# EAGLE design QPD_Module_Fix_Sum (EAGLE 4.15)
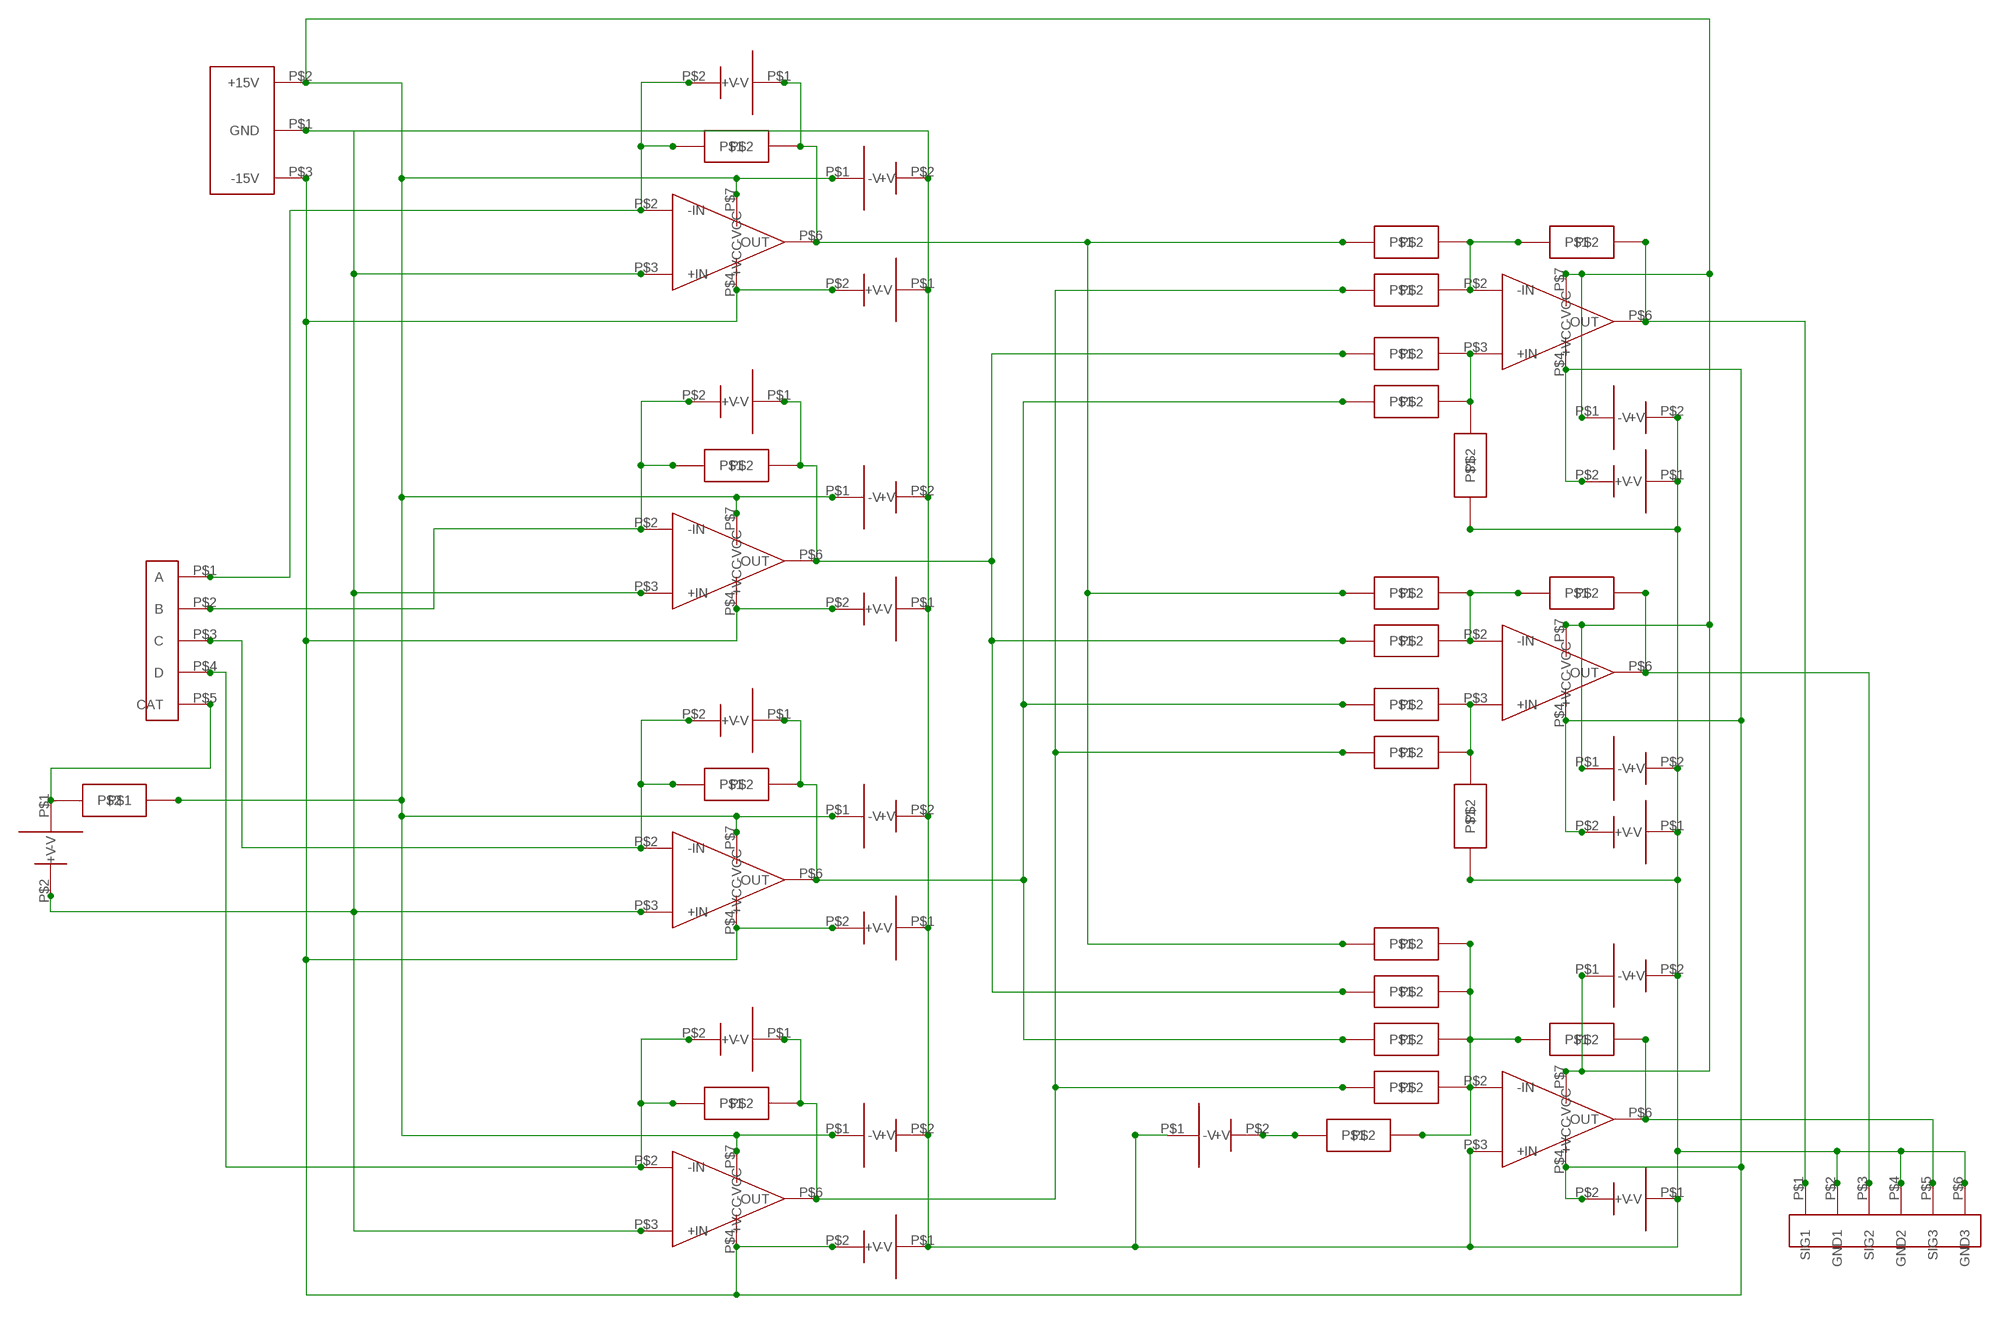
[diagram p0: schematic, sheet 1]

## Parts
U$1  OPA37GP  [OPA37GP]
U$2  OPA37GP  [OPA37GP]
U$3  OPA37GP  [OPA37GP]
U$4  OPA37GP  [OPA37GP]
U$5  OPA37GP  [OPA37GP]
U$6  OPA37GP  [OPA37GP]
U$7  OPA37GP  [OPA37GP]
U$8  PWR-CONN  [PWR-CONN]
U$9  CAP  [CAP]
U$10  RES  [RES]
U$11  CAP  [CAP]
U$12  RES  [RES]
U$13  5-TMBLK  [5-TMBLK]
U$14  CAP  [CAP]
U$15  RES  [RES]
U$16  RES  [RES]
U$17  CAP  [CAP]
U$18  6-TMBLK  [6-TMBLK]
U$19  RES  [RES]
U$20  RES  [RES]
U$21  CAP  [CAP]
U$22  CAP  [CAP]
U$23  CAP  [CAP]
U$24  CAP  [CAP]
U$25  CAP  [CAP]
U$26  CAP  [CAP]
U$27  CAP  [CAP]
U$28  CAP  [CAP]
U$29  CAP  [CAP]
U$30  RES  [RES]
U$31  RES  [RES]
U$32  RES  [RES]
U$33  RES  [RES]
U$34  RES  [RES]
U$35  RES  [RES]
U$36  RES  [RES]
U$37  RES  [RES]
U$38  RES  [RES]
U$39  RES  [RES]
U$40  RES  [RES]
U$41  RES  [RES]
U$42  RES  [RES]
U$43  RES  [RES]
U$44  RES  [RES]
U$45  RES  [RES]
U$46  RES  [RES]
U$47  CAP  [CAP]
U$48  CAP  [CAP]
U$49  CAP  [CAP]
U$50  CAP  [CAP]
U$51  CAP  [CAP]
U$52  CAP  [CAP]
U$53  CAP  [CAP]

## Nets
N$1: U$1.P$6(OUT) U$9.P$1(+V) U$10.P$2 U$32.P$1 U$34.P$1 U$42.P$1
N$2: U$19.P$1 U$53.P$2(-V)
N$4: U$13.P$5(CAT) U$20.P$2 U$21.P$1(+V)
N$6: U$5.P$3(+IN) U$32.P$2 U$33.P$2 U$38.P$2
N$7: U$1.P$3(+IN) U$2.P$3(+IN) U$3.P$3(+IN) U$4.P$3(+IN) U$7.P$3(+IN) U$8.P$1(GND) U$18.P$2(GND1) U$18.P$4(GND2) U$18.P$6(GND3) U$21.P$2(-V) U$22.P$2(-V) U$23.P$1(+V) U$24.P$2(-V) U$25.P$1(+V) U$26.P$2(-V) U$27.P$1(+V) U$28.P$1(+V) U$29.P$2(-V) U$38.P$1 U$39.P$1 U$47.P$2(-V) U$48.P$1(+V) U$49.P$2(-V) U$50.P$1(+V) U$51.P$2(-V) U$52.P$1(+V) U$53.P$1(+V)
N$8: U$1.P$2(-IN) U$9.P$2(-V) U$10.P$1 U$13.P$2(B)
N$9: U$4.P$6(OUT) U$16.P$2 U$17.P$1(+V) U$30.P$1 U$35.P$1 U$43.P$1
N$10: U$4.P$2(-IN) U$13.P$1(A) U$16.P$1 U$17.P$2(-V)
N$11: U$2.P$6(OUT) U$11.P$1(+V) U$12.P$2 U$33.P$1 U$36.P$1 U$41.P$1
N$12: U$2.P$2(-IN) U$11.P$2(-V) U$12.P$1 U$13.P$3(C)
N$13: U$3.P$6(OUT) U$14.P$1(+V) U$15.P$2 U$31.P$1 U$37.P$1 U$40.P$1
N$14: U$3.P$2(-IN) U$13.P$4(D) U$14.P$2(-V) U$15.P$1
N$15: U$5.P$2(-IN) U$30.P$2 U$31.P$2 U$44.P$1
N$17: U$6.P$3(+IN) U$36.P$2 U$37.P$2 U$39.P$2
N$19: U$7.P$2(-IN) U$19.P$2 U$40.P$2 U$41.P$2 U$42.P$2 U$43.P$2 U$46.P$1
N$21: U$1.P$7(+VCC) U$2.P$7(+VCC) U$3.P$7(+VCC) U$4.P$7(+VCC) U$5.P$7(+VCC) U$6.P$7(+VCC) U$7.P$7(+VCC) U$8.P$2(+15V) U$20.P$1 U$22.P$1(+V) U$24.P$1(+V) U$26.P$1(+V) U$29.P$1(+V) U$47.P$1(+V) U$49.P$1(+V) U$51.P$1(+V)
N$24: U$5.P$6(OUT) U$18.P$1(SIG1) U$44.P$2
N$26: U$1.P$4(-VCC) U$2.P$4(-VCC) U$3.P$4(-VCC) U$4.P$4(-VCC) U$5.P$4(-VCC) U$6.P$4(-VCC) U$7.P$4(-VCC) U$8.P$3(-15V) U$23.P$2(-V) U$25.P$2(-V) U$27.P$2(-V) U$28.P$2(-V) U$48.P$2(-V) U$50.P$2(-V) U$52.P$2(-V)
N$28: U$6.P$6(OUT) U$18.P$3(SIG2) U$45.P$2
N$29: U$7.P$6(OUT) U$18.P$5(SIG3) U$46.P$2
N$30: U$6.P$2(-IN) U$34.P$2 U$35.P$2 U$45.P$1

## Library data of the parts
U$1-U$7 = PSD Module:OPA37GP
U$8 = PSD Module:PWR-CONN
U$9 U$11 U$14 U$17 U$21-U$29 U$47-U$52 = PSD Module:CAP
U$10 U$12 U$15 U$16 U$20 U$30-U$46 = PSD Module:RES
U$13 = PSD Module:5-TMBLK
U$18 = PSD Module:6-TMBLK
U$19 = QPD Module:RES
U$53 = QPD Module:CAP

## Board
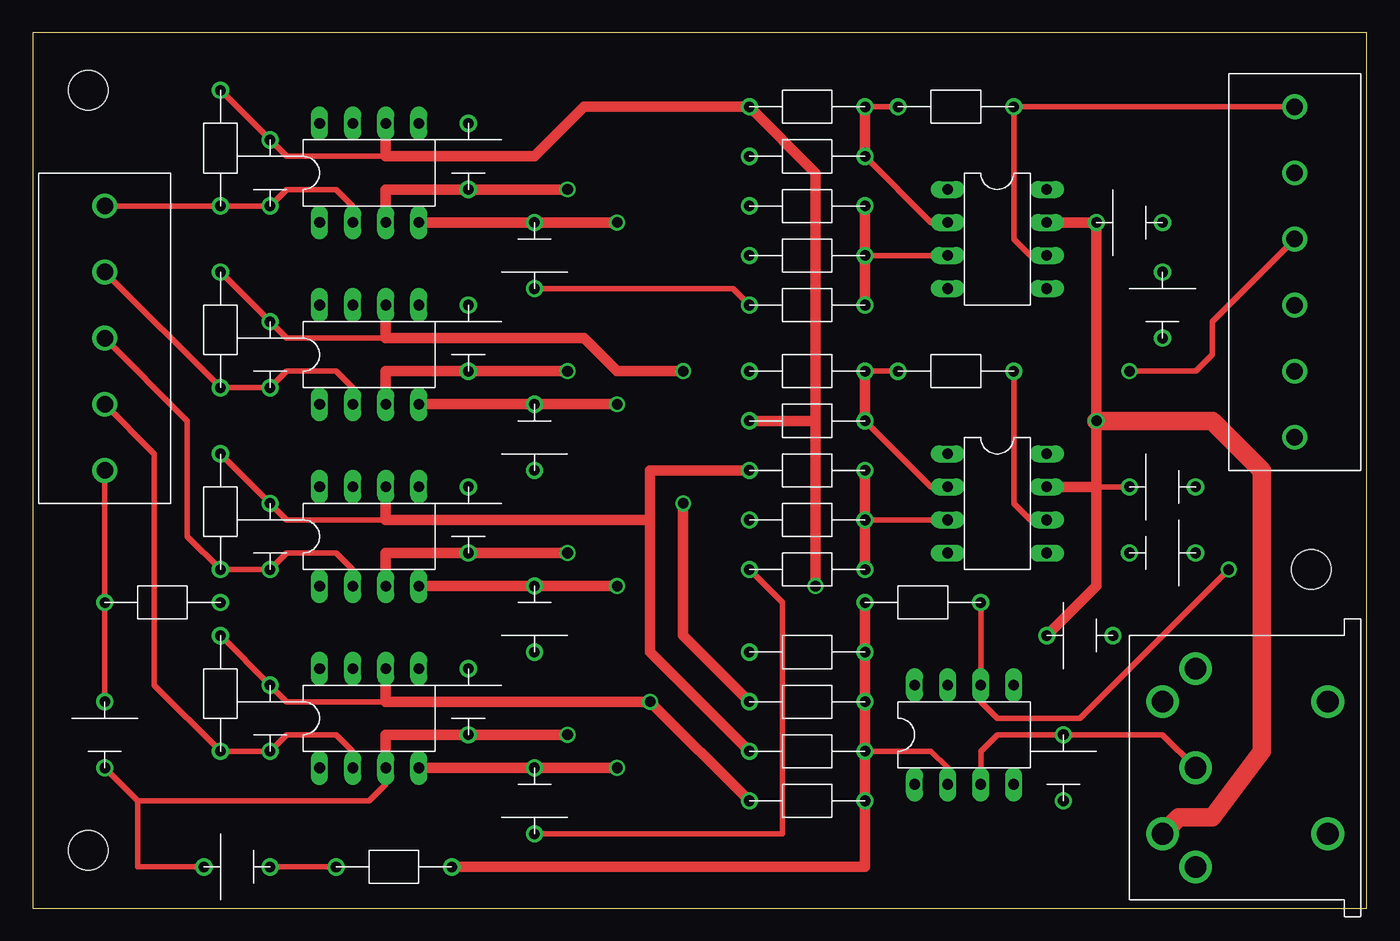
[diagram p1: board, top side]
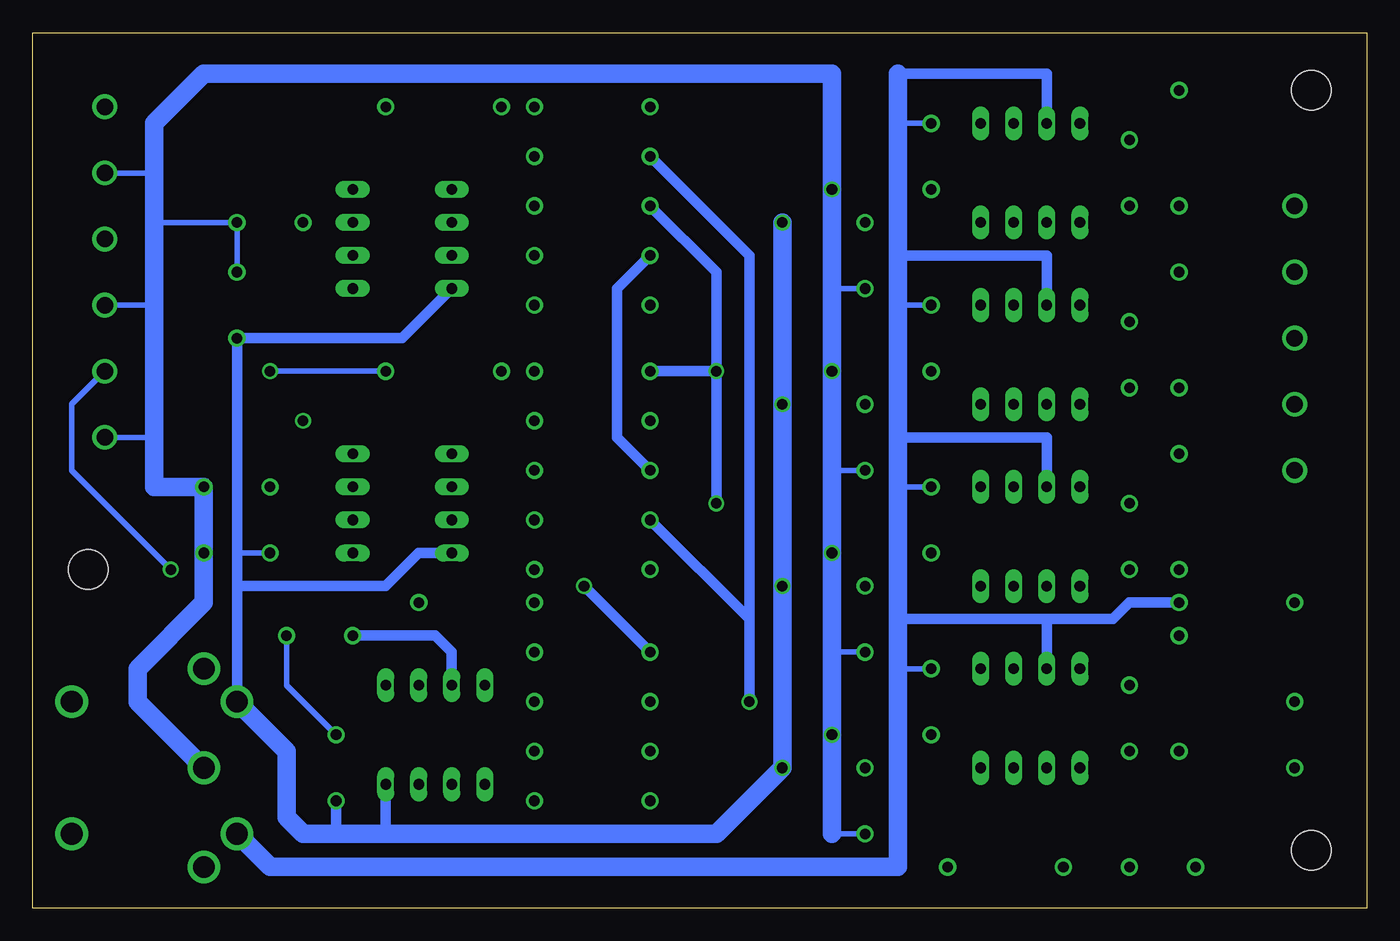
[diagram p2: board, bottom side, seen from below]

Size 102.54 x 67.3 mm. Coordinates in mm from the lower left corner, seen from the top.
Outline: 0,0 102.54,0 102.54,67.3 0,67.3 0,0
Copper layers (1*16): Top 0.035mm / dielectric 1.5mm / Bottom 0.035mm
Design rules "default": minimum track width 10mil, minimum drill 24mil, track to track 8mil, track to pad 8mil, pad to pad 8mil, via to via 8mil, smd to smd 8mil, copper to edge 40mil, drill to drill 8mil, minimum pad ring 10mil, minimum via ring 8mil, stop-mask expansion 4mil, vias tented up to drill 0mil, thermal gap 10mil
Holes 3.05 mm at 4.28,4.44 4.28,62.86 98.26,26.03

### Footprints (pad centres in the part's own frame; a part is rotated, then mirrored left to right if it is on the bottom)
OPA37GP = drill 0.813 long: P$1 -3.81,-3.81; P$2 -1.27,-3.81; P$3 1.27,-3.81; P$4 3.81,-3.81; P$5 3.81,3.81; P$6 1.27,3.81; P$7 -1.27,3.81; P$8 -3.81,3.81
PWR-CONN = drill 1.676 round: P$1 0,5.08; P$2 -5.08,7.62; P$3 5.08,7.62; P$4 -7.62,5.08; P$5 7.62,5.08; P$6 -5.08,-5.08; P$7 5.08,-5.08
CAP = drill 0.813 round: P$1 -2.54,0; P$2 2.54,0
RES = drill 0.813 round: P$1 -3.81,0; P$2 5.08,0
5-TMBLK = drill 1.27 round: P$1 -10.16,0; P$2 -5.08,0; P$3 0,0; P$4 5.08,0; P$5 10.16,0
6-TMBLK = drill 1.27 round: P$1 -12.7,0; P$2 -7.62,0; P$3 -2.54,0; P$4 2.54,0; P$5 7.62,0; P$6 12.7,0

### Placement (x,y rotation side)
U$1  25.87,42.54 0 top
U$2  25.87,28.57 0 top
U$3  25.87,14.6 0 top
U$4  25.87,56.51 0 top
U$5  74.13,51.43 270 top
U$6  74.13,31.11 270 top
U$7  71.59,13.33 0 top
U$8  94.45,10.79 90 top
U$9  18.25,42.54 270 top
U$10  14.44,43.81 90 top
U$11  18.25,28.57 270 top
U$12  14.44,29.84 90 top
U$13  5.55,43.81 270 top
U$14  18.25,14.6 270 top
U$15  14.44,15.87 90 top
U$16  14.44,57.78 90 top
U$17  18.25,56.51 270 top
U$18  96.99,48.89 270 top
U$19  27.14,3.17 0 top
U$20  10.63,23.49 180 top
U$21  5.55,13.33 270 top
U$22  33.49,15.87 270 top
U$23  38.57,8.25 90 top
U$24  33.49,29.84 270 top
U$25  38.57,22.22 90 top
U$26  33.49,43.81 270 top
U$27  38.57,36.19 90 top
U$28  38.57,50.16 90 top
U$29  33.49,57.78 270 top
U$30  58.89,61.59 0 top
U$31  58.89,57.78 0 top
U$32  58.89,53.97 0 top
U$33  58.89,50.16 0 top
U$34  58.89,41.27 0 top
U$35  58.89,37.46 0 top
U$36  58.89,33.65 0 top
U$37  58.89,29.84 0 top
U$38  58.89,46.35 0 top
U$39  58.89,26.03 0 top
U$40  58.89,8.25 0 top
U$41  58.89,12.06 0 top
U$42  58.89,15.87 0 top
U$43  58.89,19.68 0 top
U$44  70.32,61.59 0 top
U$45  70.32,41.27 0 top
U$46  67.78,23.49 0 top
U$47  84.29,52.7 0 top
U$48  86.83,46.35 270 top
U$49  86.83,32.38 0 top
U$50  86.83,27.3 180 top
U$51  80.48,20.95 0 top
U$52  79.21,10.79 270 top
U$53  15.71,3.17 0 top

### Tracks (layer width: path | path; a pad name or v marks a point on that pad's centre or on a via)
N$1  (via drill 0.81 pad 0.81)
  Top 0.406: U$10.P$2 U$9.P$1 19.52,43.81 27.14,43.81
  Top 0.813: U$1.P$6 27.14,43.81 42.38,43.81 44.92,41.27 v50,41.27 | U$42.P$1 50,20.95 v50,31.11
  Bottom 0.813: v50,41.27 v50,31.11 | v50,41.27 U$34.P$1 | v50,41.27 50,48.89 U$32.P$1
N$2
  Top 0.406: U$53.P$2 U$19.P$1
N$4
  Top 0.406: U$13.P$5 U$20.P$2 U$21.P$1
N$6
  Top 0.406: U$33.P$2 U$5.P$3
  Top 0.813: U$38.P$2 U$33.P$2 U$32.P$2
N$7  (via drill 0.81)
  Top 0.406: 8.09,8.25 U$21.P$2 | 8.09,8.25 25.87,8.25 27.14,9.52 U$3.P$3 | U$39.P$1 57.62,23.49 57.62,5.71 U$23.P$1 | U$38.P$1 53.81,47.62 U$28.P$1 | U$7.P$3 72.86,12.06 74.13,13.33 U$52.P$1 86.83,13.33 U$8.P$1 | U$53.P$1 8.09,3.17 8.09,8.25
  Top 0.813: v41.11,55.24 U$29.P$2 27.14,55.24 U$4.P$3 | v41.11,41.27 U$26.P$2 27.14,41.27 U$1.P$3 | v41.11,27.3 U$24.P$2 27.14,27.3 U$2.P$3 | v41.11,13.33 U$22.P$2 27.14,13.33 U$3.P$3
  Bottom 0.406: 41.11,19.68 U$25.P$1 | 41.11,33.65 U$27.P$1 | 41.11,47.62 U$28.P$1 | 41.11,5.71 U$23.P$1 | U$49.P$2 U$50.P$1 | U$47.P$2 U$48.P$1 U$47.P$2 | 93.18,52.7 U$47.P$2 | U$51.P$2 83.02,17.14 U$52.P$1 | 93.18,56.51 U$18.P$2 | 93.18,46.35 U$18.P$4 | 93.18,36.19 U$18.P$6
  Bottom 1.422: 41.11,5.71 v41.11,13.33 41.11,19.68 v41.11,27.3 41.11,33.65 v41.11,41.27 41.11,47.62 v41.11,55.24 41.11,64.13 89.37,64.13 93.18,60.32 93.18,56.51 93.18,52.7 93.18,46.35 93.18,36.19 93.18,32.38 U$49.P$2 U$50.P$1 89.37,23.49 94.45,18.41 94.45,15.87 U$8.P$1
N$8
  Top 0.406: U$1.P$2 24.6,40 23.33,41.27 19.52,41.27 U$9.P$2 U$10.P$1 U$13.P$2
N$9  (via drill 0.81 pad 0.81)
  Top 0.406: U$16.P$2 U$17.P$1 19.52,57.78 27.14,57.78
  Top 0.813: U$4.P$6 27.14,57.78 38.57,57.78 42.38,61.59 U$30.P$1 60.16,56.51 60.16,37.46 | v60.16,24.76 60.16,37.46 | 60.16,37.46 U$35.P$1
  Bottom 0.813: U$43.P$1 v60.16,24.76
N$10
  Top 0.406: U$4.P$2 24.6,53.97 23.33,55.24 19.52,55.24 U$17.P$2 U$16.P$1 U$13.P$1
N$11
  Top 0.406: U$12.P$2 U$11.P$1 19.52,29.84 27.14,29.84
  Top 0.813: U$2.P$6 27.14,29.84 47.46,29.84 | 47.46,29.84 47.46,33.65 U$36.P$1 | U$41.P$1 47.46,19.68 47.46,29.84
  Bottom 0.813: U$33.P$1 57.62,47.62 57.62,36.19 U$36.P$1
N$12
  Top 0.406: U$2.P$2 24.6,26.03 23.33,27.3 19.52,27.3 U$11.P$2 U$12.P$1 11.9,28.57 11.9,37.46 U$13.P$3
N$13  (via drill 0.81 pad 0.81)
  Top 0.406: U$15.P$2 U$14.P$1 19.52,15.87 27.14,15.87
  Top 0.813: U$3.P$6 27.14,15.87 v47.46,15.87 U$40.P$1
  Bottom 0.813: U$37.P$1 47.46,22.22 v47.46,15.87 47.46,50.16 U$31.P$1
N$14
  Top 0.406: U$3.P$2 24.6,12.06 23.33,13.33 19.52,13.33 U$14.P$2 U$15.P$1 9.36,17.14 9.36,34.92 U$13.P$4
N$15
  Top 0.406: U$5.P$2 69.05,52.7 U$31.P$2 | U$30.P$2 U$44.P$1
  Top 0.813: U$31.P$2 U$30.P$2
N$17
  Top 0.406: U$37.P$2 U$6.P$3
  Top 0.813: U$39.P$2 U$37.P$2 U$36.P$2
N$19
  Top 0.406: U$41.P$2 69.05,12.06 70.32,10.79 U$7.P$2
  Top 0.813: U$46.P$1 U$43.P$2 U$42.P$2 U$41.P$2 U$40.P$2 63.97,3.17 U$19.P$2
N$21  (via drill 0.81 pad 0.81)
  Top 0.406: 81.75,32.38 U$49.P$1
  Top 0.813: 81.75,32.38 v81.75,37.46 U$47.P$1 U$5.P$7 | 81.75,32.38 U$6.P$7 | 81.75,32.38 81.75,24.76 U$51.P$1
  Top 1.422: U$8.P$2 88.1,6.98 90.64,6.98 94.45,12.06 94.45,33.65 90.64,37.46 v81.75,37.46
  Bottom 0.406: 36.03,60.32 U$29.P$1 | 36.03,46.35 U$26.P$1 | 36.03,32.38 U$24.P$1 | 36.03,18.41 U$22.P$1
  Bottom 0.813: U$1.P$7 24.6,50.16 36.03,50.16 | U$4.P$7 24.6,64.13 36.03,64.13 | U$2.P$7 24.6,36.19 36.03,36.19 | 24.6,22.22 U$3.P$7 | 24.6,22.22 36.03,22.22 | U$20.P$1 18.25,23.49 19.52,22.22 24.6,22.22 | U$51.P$1 71.59,20.95 70.32,19.68 U$7.P$7
  Bottom 1.422: 36.03,64.13 36.03,60.32 36.03,50.16 36.03,46.35 36.03,36.19 36.03,32.38 36.03,22.22 36.03,18.41 36.03,3.17 84.29,3.17 U$8.P$2
N$24
  Top 0.406: U$5.P$6 76.67,50.16 75.4,51.43 U$44.P$2 U$18.P$1
N$26  (via drill 0.81 pad 0.81)
  Top 0.813: U$3.P$4 U$23.P$2 v44.92,10.79 | v44.92,52.7 U$28.P$2 U$4.P$4 | v44.92,38.73 U$27.P$2 U$1.P$4 | v44.92,24.76 U$25.P$2 U$2.P$4
  Bottom 0.406: 86.83,27.3 U$50.P$2
  Bottom 0.813: U$8.P$3 86.83,24.76 | 86.83,24.76 86.83,27.3 U$48.P$2 74.13,43.81 U$5.P$4 | U$6.P$4 72.86,27.3 75.4,24.76 86.83,24.76 | 75.4,5.71 U$7.P$4 | 79.21,5.71 U$52.P$2
  Bottom 1.422: U$8.P$3 83.02,12.06 83.02,6.98 81.75,5.71 79.21,5.71 75.4,5.71 50,5.71 v44.92,10.79 v44.92,24.76 v44.92,38.73 v44.92,52.7
N$28  (via drill 0.81 pad 0.81)
  Top 0.406: U$45.P$2 75.4,31.11 76.67,29.84 U$6.P$6 | U$18.P$3 90.64,45.08 90.64,42.54 89.37,41.27 v84.29,41.27
  Bottom 0.406: U$45.P$2 v84.29,41.27
N$29  (via drill 0.81 pad 0.81)
  Top 0.406: U$7.P$6 U$46.P$2 U$7.P$6 | U$7.P$6 72.86,15.87 74.13,14.6 80.48,14.6 v91.91,26.03
  Bottom 0.406: U$18.P$5 99.53,38.73 99.53,33.65 v91.91,26.03
N$30
  Top 0.406: U$6.P$2 69.05,32.38 U$35.P$2 | U$34.P$2 U$45.P$1
  Top 0.813: U$35.P$2 U$34.P$2

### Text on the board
tDocu: Lang Lab | QPD-002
